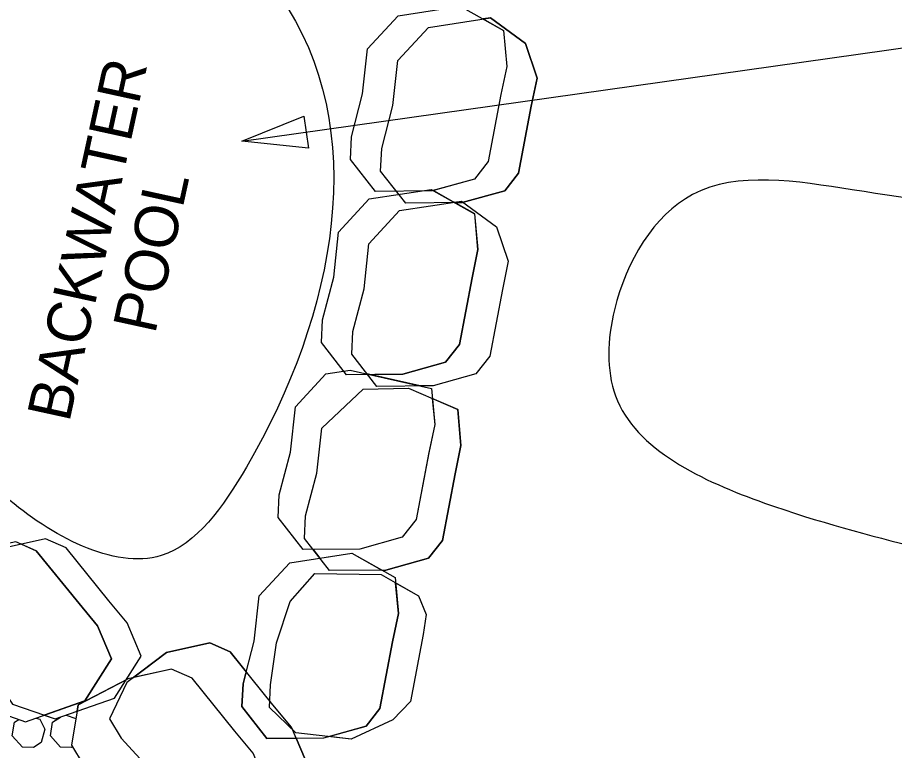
# Model space of a CAD drawing. Extents: x 2126110 to 2128246, y 1804858 to 1811658.
# Drawn here: x 2126648.9 to 2127053.6, y 1809146 to 1809484.3 of the extents above; entities that cross this region are included whole.
import ezdxf

# ---------------------------------------------------------------- set-up
doc = ezdxf.new("R2010")
doc.units = 0
for name, color, linetype in [('1', 7, 'Continuous'), ('DET-EARTH', 7, 'Continuous'), ('Old_Level_1', 7, 'Continuous'), ('Old_Level_41', 7, 'Continuous')]:
    doc.layers.add(name, color=color, linetype=linetype)

msp = doc.modelspace()

# ---------------------------------------------------------------- linework, layer by layer
at = {"layer": '1'}
msp.add_line((2126752.41, 1809427.2), (2127380.49, 1809515.77), dxfattribs=at)
msp.add_lwpolyline([(2126783.17, 1809423.96), (2126752.41, 1809427.2), (2126781.07, 1809438.81)], close=True, dxfattribs=at)
at = {"layer": 'DET-EARTH'}
for points in [[(2126816.98, 1809423.87), (2126822.14, 1809443.63), (2126824.38, 1809464.44), (2126838.51, 1809479.73), (2126867.15, 1809484.15), (2126883.31, 1809472.21), (2126888.68, 1809456.33), (2126885.98, 1809443.32), (2126880.12, 1809412.48), (2126873.73, 1809404.33), (2126854.07, 1809398.84), (2126854.07, 1809398.84), (2126828.01, 1809398.61), (2126816.46, 1809413.43), (2126816.98, 1809423.87)], [(2126803.65, 1809339.31), (2126808.81, 1809359.07), (2126811.06, 1809379.88), (2126825.18, 1809395.17), (2126853.82, 1809399.59), (2126869.98, 1809387.66), (2126875.35, 1809371.78), (2126872.65, 1809358.76), (2126866.79, 1809327.92), (2126860.4, 1809319.78), (2126840.74, 1809314.28), (2126840.74, 1809314.28), (2126814.68, 1809314.06), (2126803.13, 1809328.87), (2126803.65, 1809339.31)], [(2126781.84, 1809254.28), (2126787, 1809274.04), (2126789.25, 1809294.84), (2126808.33, 1809312.71), (2126829.3, 1809313.16), (2126852.02, 1809303.31), (2126853.54, 1809286.74), (2126850.85, 1809273.73), (2126844.98, 1809242.89), (2126838.59, 1809234.74), (2126818.93, 1809229.24), (2126818.93, 1809229.24), (2126792.87, 1809229.02), (2126781.32, 1809243.83), (2126781.84, 1809254.28)], [(2126607.26, 1809198.38), (2126621.13, 1809183.39), (2126632.93, 1809166.11), (2126652.59, 1809159.29), (2126679.94, 1809168.91), (2126692.27, 1809188.26), (2126685.8, 1809203.58), (2126677.27, 1809213.79), (2126657.56, 1809238.21), (2126648.08, 1809242.38), (2126628.15, 1809237.96), (2126628.15, 1809237.96), (2126605.07, 1809225.86), (2126601.87, 1809207.34), (2126607.26, 1809198.38)], [(2126620.99, 1809199.66), (2126634.85, 1809184.68), (2126646.65, 1809167.39), (2126666.31, 1809160.57), (2126693.66, 1809170.19), (2126706, 1809189.54), (2126699.52, 1809204.86), (2126691, 1809215.07), (2126671.28, 1809239.49), (2126661.81, 1809243.67), (2126641.87, 1809239.24), (2126641.87, 1809239.24), (2126619.16, 1809225.06), (2126615.6, 1809208.63), (2126620.99, 1809199.66)], [(2126765.7, 1809176.33), (2126768.38, 1809195.73), (2126774.71, 1809214.84), (2126786.16, 1809227.68), (2126816.65, 1809227.26), (2126833.92, 1809217.37), (2126837.4, 1809208.79), (2126836.06, 1809199.48), (2126830.19, 1809168.64), (2126822.16, 1809160.24), (2126802.79, 1809151.29), (2126802.79, 1809151.29), (2126777.3, 1809154.22), (2126765.18, 1809165.88), (2126765.7, 1809176.33)], [(2126696.78, 1809151.64), (2126710.64, 1809136.66), (2126722.44, 1809119.37), (2126742.1, 1809112.55), (2126769.45, 1809122.16), (2126781.79, 1809141.52), (2126775.31, 1809156.84), (2126766.79, 1809167.05), (2126747.07, 1809191.47), (2126737.6, 1809195.65), (2126717.66, 1809191.22), (2126717.66, 1809191.22), (2126699.3, 1809177.33), (2126691.39, 1809160.61), (2126696.78, 1809151.64)], [(2126679.14, 1809139.54), (2126693, 1809124.56), (2126704.81, 1809107.27), (2126724.47, 1809100.45), (2126751.81, 1809110.07), (2126764.14, 1809129.43), (2126757.67, 1809144.74), (2126749.15, 1809154.95), (2126729.44, 1809179.37), (2126719.95, 1809183.54), (2126700.02, 1809179.12), (2126700.02, 1809179.12), (2126676.95, 1809167.02), (2126673.74, 1809148.5), (2126679.14, 1809139.54)]]:
    msp.add_lwpolyline(points, dxfattribs=at)
for points in [[(2126607.67, 1809405.83), (2126618.41, 1809454.94), (2126650.78, 1809501.03), (2126688.47, 1809521.66), (2126738.85, 1809522.03), (2126769.82, 1809494.4), (2126754.53, 1809276.75), (2126715.26, 1809236.01), (2126643.36, 1809263.1), (2126612.06, 1809300.25), (2126598.49, 1809332.37), (2126607.32, 1809404.19)], [(2127174.54, 1809209.38), (2127065.12, 1809239.39), (2126993.61, 1809260.22), (2126924.84, 1809309.69), (2126924.37, 1809349.44), (2126960.39, 1809402.56), (2127034.11, 1809404.75), (2127116.95, 1809392.75), (2127227, 1809365.65), (2127288.04, 1809312.55), (2127296.13, 1809286.77), (2127293.11, 1809265.12), (2127270.83, 1809231.04), (2127231.79, 1809206.02), (2127174.54, 1809209.38)]]:
    msp.add_spline(points, degree=3, dxfattribs=at)
at = {"layer": 'Old_Level_1'}
msp.add_line((2126671.31, 1809162.26), (2126675.86, 1809160.77), dxfattribs=at)
for points in [[(2126668.79, 1809147.58), (2126664.05, 1809152.75), (2126665.06, 1809159.12), (2126668.76, 1809161.39)], [(2126651.2, 1809147.54), (2126646.45, 1809152.71), (2126647.47, 1809159.08), (2126649.54, 1809160.35)], [(2126657.47, 1809160.99), (2126659.18, 1809160.44), (2126661.56, 1809155.85), (2126659.75, 1809149.73), (2126656.28, 1809147.43), (2126651.2, 1809147.55)], [(2126674.19, 1809147.68), (2126673.87, 1809147.47), (2126668.79, 1809147.59)]]:
    msp.add_lwpolyline(points, dxfattribs=at)
at = {"layer": 'Old_Level_41'}
for p, q in [((2126867.16, 1809484.15), (2126863.7, 1809483.61)), ((2126863.7, 1809483.61), (2126873.18, 1809478.29)), ((2126883.31, 1809472.21), (2126867.16, 1809484.15)), ((2126873.18, 1809478.29), (2126874.7, 1809461.72)), ((2126888.68, 1809456.33), (2126883.31, 1809472.21)), ((2126874.7, 1809461.72), (2126872, 1809448.7)), ((2126885.98, 1809443.32), (2126888.68, 1809456.33)), ((2126872, 1809448.7), (2126866.14, 1809417.87)), ((2126880.12, 1809412.48), (2126885.98, 1809443.32)), ((2126866.14, 1809417.87), (2126859.75, 1809409.72)), ((2126873.73, 1809404.33), (2126880.12, 1809412.48)), ((2126859.75, 1809409.72), (2126840.82, 1809404.43)), ((2126840.82, 1809404.43), (2126850.82, 1809398.81)), ((2126854.07, 1809398.83), (2126873.73, 1809404.33)), ((2126850.37, 1809399.06), (2126853.83, 1809399.59)), ((2126859.85, 1809393.73), (2126850.37, 1809399.06)), ((2126850.82, 1809398.81), (2126854.07, 1809398.83)), ((2126853.83, 1809399.59), (2126869.98, 1809387.66)), ((2126861.37, 1809377.16), (2126859.85, 1809393.73)), ((2126869.98, 1809387.66), (2126875.35, 1809371.78)), ((2126858.67, 1809364.15), (2126861.37, 1809377.16)), ((2126875.35, 1809371.78), (2126872.65, 1809358.76)), ((2126852.81, 1809333.31), (2126858.67, 1809364.15)), ((2126872.65, 1809358.76), (2126866.79, 1809327.92)), ((2126846.42, 1809325.16), (2126852.81, 1809333.31)), ((2126866.79, 1809327.92), (2126860.4, 1809319.78)), ((2126826.76, 1809319.66), (2126846.42, 1809325.16)), ((2126802.46, 1809321.6), (2126839.88, 1809313.04)), ((2126811.48, 1809319.53), (2126810.18, 1809319.83)), ((2126810.18, 1809319.83), (2126810.42, 1809319.53)), ((2126810.42, 1809319.53), (2126811.48, 1809319.53)), ((2126811.48, 1809319.53), (2126826.76, 1809319.66)), ((2126834.68, 1809314.23), (2126811.48, 1809319.53)), ((2126860.4, 1809319.78), (2126840.74, 1809314.28)), ((2126840.74, 1809314.28), (2126834.68, 1809314.23)), ((2126840.74, 1809314.28), (2126840.74, 1809314.28)), ((2126852.02, 1809303.31), (2126840.31, 1809308.38)), ((2126840.31, 1809308.38), (2126841.4, 1809296.47)), ((2126853.54, 1809286.74), (2126852.02, 1809303.31)), ((2126841.4, 1809296.47), (2126838.71, 1809283.45)), ((2126850.85, 1809273.72), (2126853.54, 1809286.74)), ((2126838.71, 1809283.45), (2126832.85, 1809252.62)), ((2126844.98, 1809242.89), (2126850.85, 1809273.72)), ((2126832.85, 1809252.62), (2126826.46, 1809244.47)), ((2126661.81, 1809243.67), (2126650.74, 1809241.21)), ((2126671.28, 1809239.49), (2126661.81, 1809243.67)), ((2126826.46, 1809244.47), (2126806.79, 1809238.97)), ((2126838.6, 1809234.74), (2126844.98, 1809242.89)), ((2126650.74, 1809241.21), (2126657.56, 1809238.21)), ((2126657.56, 1809238.21), (2126677.27, 1809213.78)), ((2126691, 1809215.07), (2126671.28, 1809239.49)), ((2126806.79, 1809238.97), (2126785.26, 1809238.79)), ((2126785.26, 1809238.79), (2126788.38, 1809234.78)), ((2126806.79, 1809238.97), (2126806.79, 1809238.97)), ((2126788.38, 1809234.78), (2126803.15, 1809237.05)), ((2126803.15, 1809237.05), (2126817.08, 1809229.22)), ((2126818.93, 1809229.24), (2126838.6, 1809234.74)), ((2126817.08, 1809229.22), (2126818.93, 1809229.24)), ((2126824.67, 1809209.24), (2126823.37, 1809223.41)), ((2126823.37, 1809223.41), (2126833.93, 1809217.37)), ((2126677.27, 1809213.78), (2126685.8, 1809203.58)), ((2126699.52, 1809204.86), (2126691, 1809215.07)), ((2126833.93, 1809217.37), (2126837.4, 1809208.79)), ((2126821.98, 1809196.23), (2126824.67, 1809209.24)), ((2126837.4, 1809208.79), (2126836.06, 1809199.48)), ((2126685.8, 1809203.58), (2126692.27, 1809188.26)), ((2126706, 1809189.54), (2126699.52, 1809204.86)), ((2126836.06, 1809199.48), (2126830.19, 1809168.64)), ((2126717.66, 1809191.22), (2126737.6, 1809195.64)), ((2126737.6, 1809195.64), (2126747.07, 1809191.47)), ((2126816.11, 1809165.39), (2126821.98, 1809196.23)), ((2126699.02, 1809178.59), (2126706, 1809189.54)), ((2126702.35, 1809179.64), (2126717.66, 1809191.22)), ((2126747.07, 1809191.47), (2126754.43, 1809182.36)), ((2126692.27, 1809188.26), (2126679.94, 1809168.91)), ((2126719.96, 1809183.54), (2126702.35, 1809179.64)), ((2126729.44, 1809179.37), (2126719.96, 1809183.54)), ((2126754.43, 1809182.36), (2126752.97, 1809176.78)), ((2126676.95, 1809167.02), (2126699.02, 1809178.59)), ((2126749.15, 1809154.95), (2126729.44, 1809179.37)), ((2126752.97, 1809176.78), (2126752.45, 1809166.33)), ((2126679.94, 1809168.91), (2126661.24, 1809162.33)), ((2126676.45, 1809164.13), (2126676.95, 1809167.02)), ((2126752.45, 1809166.33), (2126764.01, 1809151.52)), ((2126809.73, 1809157.24), (2126816.11, 1809165.39)), ((2126830.19, 1809168.64), (2126822.16, 1809160.24)), ((2126661.24, 1809162.33), (2126666.32, 1809160.57)), ((2126666.32, 1809160.57), (2126676.45, 1809164.13)), ((2126792.63, 1809152.46), (2126809.73, 1809157.24)), ((2126822.16, 1809160.24), (2126802.79, 1809151.29)), ((2126757.67, 1809144.74), (2126749.15, 1809154.95)), ((2126764.01, 1809151.52), (2126777.51, 1809151.63)), ((2126777.51, 1809151.63), (2126781.79, 1809141.52)), ((2126802.79, 1809151.29), (2126792.63, 1809152.46)), ((2126802.79, 1809151.29), (2126802.79, 1809151.29))]:
    msp.add_line(p, q, dxfattribs=at)
for points in [[(2126802.99, 1809429.26), (2126808.16, 1809449.02), (2126810.4, 1809469.82), (2126824.52, 1809485.11), (2126853.17, 1809489.53), (2126873.17, 1809478.29), (2126874.7, 1809461.72), (2126872, 1809448.7), (2126866.14, 1809417.87), (2126859.75, 1809409.72), (2126840.08, 1809404.22), (2126840.08, 1809404.22), (2126814.03, 1809404), (2126802.48, 1809418.81), (2126802.99, 1809429.26)], [(2126789.67, 1809344.7), (2126794.83, 1809364.46), (2126797.07, 1809385.26), (2126811.19, 1809400.56), (2126839.84, 1809404.98), (2126859.84, 1809393.73), (2126861.37, 1809377.16), (2126858.67, 1809364.15), (2126852.81, 1809333.31), (2126846.42, 1809325.16), (2126826.75, 1809319.67), (2126826.75, 1809319.67), (2126800.7, 1809319.44), (2126789.15, 1809334.26), (2126789.67, 1809344.7)], [(2126769.7, 1809264.01), (2126774.86, 1809283.76), (2126777.11, 1809304.57), (2126791.23, 1809319.87), (2126802.46, 1809321.6)], [(2126839.88, 1809313.04), (2126841.4, 1809296.47), (2126838.71, 1809283.46), (2126832.84, 1809252.62), (2126826.46, 1809244.47), (2126806.79, 1809238.97), (2126806.79, 1809238.97), (2126780.74, 1809238.75), (2126769.18, 1809253.56), (2126769.7, 1809264.01)], [(2126607.26, 1809198.38), (2126621.13, 1809183.39), (2126632.93, 1809166.11), (2126652.59, 1809159.29), (2126679.94, 1809168.91), (2126692.27, 1809188.26), (2126685.8, 1809203.58), (2126677.27, 1809213.79), (2126657.56, 1809238.21), (2126648.08, 1809242.38), (2126628.15, 1809237.96), (2126628.15, 1809237.96), (2126605.07, 1809225.86), (2126601.87, 1809207.34), (2126607.26, 1809198.38)], [(2126752.97, 1809176.78), (2126758.13, 1809196.54), (2126760.38, 1809217.34), (2126774.5, 1809232.64), (2126803.15, 1809237.05), (2126823.15, 1809225.81), (2126824.67, 1809209.24), (2126821.98, 1809196.23), (2126816.11, 1809165.39), (2126809.73, 1809157.24), (2126790.06, 1809151.74), (2126790.06, 1809151.74), (2126764.01, 1809151.52), (2126752.45, 1809166.33), (2126752.97, 1809176.78)], [(2126679.14, 1809139.54), (2126693, 1809124.56), (2126704.81, 1809107.27), (2126724.47, 1809100.45), (2126751.81, 1809110.07), (2126764.14, 1809129.43), (2126757.67, 1809144.74), (2126749.15, 1809154.95), (2126729.44, 1809179.37), (2126719.95, 1809183.54), (2126700.02, 1809179.12), (2126700.02, 1809179.12), (2126676.95, 1809167.02), (2126673.74, 1809148.5), (2126679.14, 1809139.54)]]:
    msp.add_lwpolyline(points, dxfattribs=at)

# ---------------------------------------------------------------- texts
at = {"layer": 'DET-EARTH'}
for s, p in [('BACKWATER', (2126672.75, 1809297.06)), ('POOL', (2126712.36, 1809337.8))]:
    msp.add_text(s, height=20, rotation=77.6736, dxfattribs=at).set_placement(p)

doc.saveas('drawing.dxf')
